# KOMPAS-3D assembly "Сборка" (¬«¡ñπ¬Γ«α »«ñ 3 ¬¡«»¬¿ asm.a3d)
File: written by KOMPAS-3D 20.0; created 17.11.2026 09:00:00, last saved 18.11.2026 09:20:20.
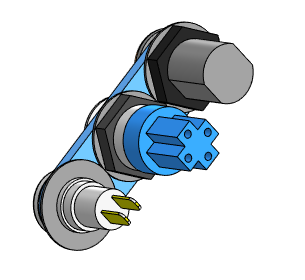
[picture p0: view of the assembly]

Document properties: Полное имя файла: D:\RicWork\Project-EPS32\box_compas\сборки компонентов\кондуктор под 3 кнопки asm.a3d

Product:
- Part/product: Сборка
    Масса: 0.0580575
  - Component [detail]: Деталь  | Масса: 0.00636192; source file: ..\корпус\кондуктор под 3 кнопки.m3d
  - Component [detail]: Деталь  | Масса: 0.0102126; source file: ..\переключатели и кнопки\button_DS-316.m3d
  - Component [assembly]: Сборка  | Масса: 0.023656; source file: ..\переключатели и кнопки\button_momentary self-reset 12 asm.a3d
  - Component [detail]: Деталь  | Масса: 0.017827; source file: ..\разъемы\USB-C_Type-C 6pin.m3d

Referenced files in D:\RicWork\Project-EPS32\box_compas\переключатели и кнопки\: button_DS-316.m3d, button_momentary self-reset 12 asm.a3d
Referenced files in D:\RicWork\Project-EPS32\box_compas\разъемы\: USB-C_Type-C 6pin.m3d
Referenced files in D:\RicWork\Project-EPS32\box_compas\корпус\: кондуктор под 3 кнопки.m3d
